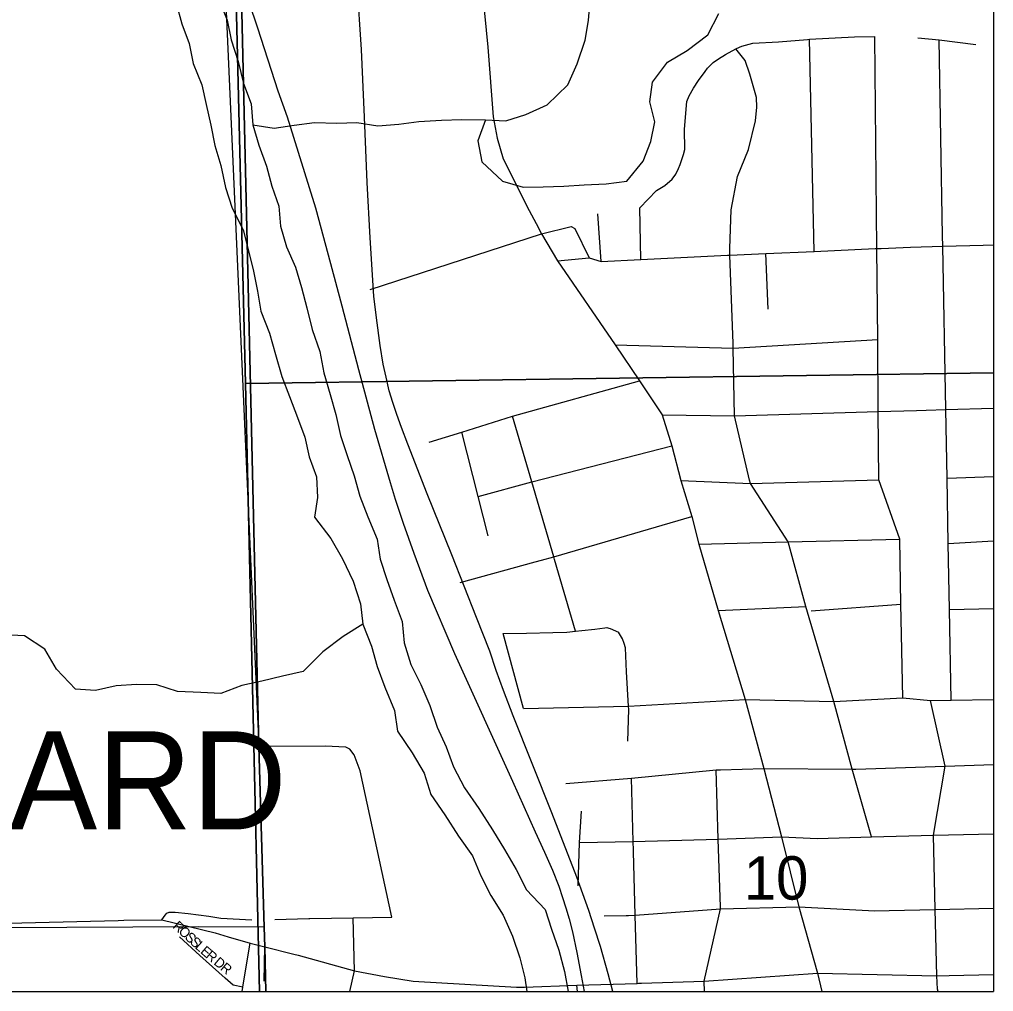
# Model space of a CAD drawing. Extents: x -37878.7 to -37844.7, y -19791.4 to -19769.4.
# Drawn here: x -37870.09 to -37869.15, y -19777.385 to -19776.447 of the extents above; entities that cross this region are included whole.
import ezdxf

# ---------------------------------------------------------------- set-up
doc = ezdxf.new("R2010")
doc.units = 0
for name, color, linetype in [('Default', 7, 'Continuous'), ('GM_X_City_Street', 7, 'Continuous'), ('GM_X_Corporation', 7, 'Continuous'), ('GM_X_Corporation_Text', 7, 'Continuous'), ('GM_X_County_Road', 7, 'Continuous'), ('GM_X_Major_River', 7, 'Continuous'), ('GM_X_Minor_River', 7, 'Continuous'), ('GM_X_Rail_Line', 7, 'Continuous'), ('GM_X_Section', 7, 'Continuous'), ('GM_X_Section_Text', 7, 'Continuous'), ('GM_X_State_Route', 7, 'Continuous'), ('GM_X_Township', 7, 'Continuous'), ('GM_X_US_Route', 7, 'Continuous'), ('SH_Data', 7, 'Continuous')]:
    doc.layers.add(name, color=color, linetype=linetype)

msp = doc.modelspace()

# ---------------------------------------------------------------- linework, layer by layer
at = {"layer": 'Default'}
msp.add_lwpolyline([(-37869.89171, -19777.37255), (-37869.91613, -19777.35058), (-37869.93578, -19777.3327)], dxfattribs=at)
at = {"layer": 'GM_X_City_Street'}
for points in [[(-37869.42351, -19776.49143), (-37869.42092, -19776.48904), (-37869.41566, -19776.4854), (-37869.40897, -19776.48136), (-37869.399, -19776.47578), (-37869.3983, -19776.47539), (-37869.39318, -19776.47327), (-37869.38251, -19776.47039), (-37869.35791, -19776.46895), (-37869.32991, -19776.46666), (-37869.32802, -19776.46656), (-37869.28447, -19776.46427), (-37869.26478, -19776.46373)], [(-37869.32333, -19776.67115), (-37869.32802, -19776.46656)], [(-37869.23922, -19777.04078), (-37869.2398, -19777.01155), (-37869.24069, -19776.94897), (-37869.26114, -19776.89148), (-37869.26153, -19776.82581), (-37869.26194, -19776.75609), (-37869.2628, -19776.66844), (-37869.26478, -19776.46373)], [(-37869.22341, -19776.46526), (-37869.20289, -19776.46697), (-37869.1675, -19776.4717)], [(-37869.19944, -19776.6562), (-37869.19944, -19776.65608), (-37869.20289, -19776.46697)], [(-37869.40479, -19776.66886), (-37869.40478, -19776.66853), (-37869.40349, -19776.63102), (-37869.39723, -19776.59891), (-37869.38663, -19776.57275), (-37869.37987, -19776.54519), (-37869.37873, -19776.53205), (-37869.37902, -19776.52275), (-37869.38537, -19776.50014), (-37869.38993, -19776.48698), (-37869.399, -19776.47578)], [(-37869.49166, -19776.6293), (-37869.47542, -19776.61251), (-37869.46759, -19776.60773), (-37869.46055, -19776.60145), (-37869.45683, -19776.59662), (-37869.45439, -19776.59136), (-37869.45277, -19776.58751), (-37869.44932, -19776.57759), (-37869.44803, -19776.57296), (-37869.44856, -19776.5532), (-37869.44624, -19776.52652), (-37869.44402, -19776.52122), (-37869.43976, -19776.51373), (-37869.4349, -19776.50624), (-37869.42854, -19776.49756), (-37869.42623, -19776.49441), (-37869.42356, -19776.49147), (-37869.42351, -19776.49143)], [(-37869.4907, -19776.67899), (-37869.49166, -19776.6293)], [(-37869.52896, -19776.68086), (-37869.53207, -19776.63498)], [(-37869.5864, -19776.65411), (-37869.5578, -19776.64725), (-37869.55417, -19776.64925), (-37869.54045, -19776.67757)], [(-37869.75193, -19776.70793), (-37869.5864, -19776.65411)], [(-37869.19128, -19777.10438), (-37869.19287, -19777.01691), (-37869.19403, -19776.95308), (-37869.19518, -19776.89004), (-37869.19638, -19776.82384), (-37869.19925, -19776.66614), (-37869.19944, -19776.6562)], [(-37869.2586, -19776.66826), (-37869.23057, -19776.667), (-37869.19925, -19776.66614), (-37869.16047, -19776.66507), (-37869.15036, -19776.66493)], [(-37869.57101, -19776.68032), (-37869.54045, -19776.67757), (-37869.52896, -19776.68086), (-37869.4907, -19776.67899), (-37869.40703, -19776.6749), (-37869.40482, -19776.6748), (-37869.36994, -19776.67324), (-37869.32333, -19776.67115), (-37869.26447, -19776.66852), (-37869.2628, -19776.66844), (-37869.2586, -19776.66826)], [(-37869.26824, -19777.23612), (-37869.2868, -19777.17084), (-37869.30447, -19777.10557), (-37869.33142, -19777.01394), (-37869.34849, -19776.95136), (-37869.38493, -19776.8953), (-37869.38593, -19776.89191), (-37869.40027, -19776.82999), (-37869.40148, -19776.76467), (-37869.40157, -19776.76015), (-37869.40482, -19776.6748), (-37869.40491, -19776.67248), (-37869.40479, -19776.66886)], [(-37869.36774, -19776.72706), (-37869.36994, -19776.67324)], [(-37869.51542, -19776.76123), (-37869.40148, -19776.76467), (-37869.26194, -19776.75609)], [(-37869.69494, -19776.85545), (-37869.66332, -19776.84557), (-37869.61435, -19776.83027), (-37869.49206, -19776.79597)], [(-37869.57392, -19776.96853), (-37869.57392, -19776.96853), (-37869.57468, -19776.96591), (-37869.59589, -19776.89341), (-37869.61435, -19776.83027)], [(-37869.63796, -19776.94554), (-37869.64759, -19776.90758), (-37869.66332, -19776.84557)], [(-37869.64759, -19776.90758), (-37869.59589, -19776.89341), (-37869.46062, -19776.85884)], [(-37869.45194, -19776.89238), (-37869.38493, -19776.8953), (-37869.26114, -19776.89148)], [(-37869.19518, -19776.89004), (-37869.15036, -19776.88847)], [(-37869.58645, -19776.96916), (-37869.57468, -19776.96591), (-37869.44146, -19776.92711)], [(-37869.43457, -19776.95376), (-37869.34849, -19776.95136), (-37869.24069, -19776.94897)], [(-37869.19403, -19776.95308), (-37869.15036, -19776.95056)], [(-37869.66481, -19776.99077), (-37869.59267, -19776.97087), (-37869.58645, -19776.96916)], [(-37869.5537, -19777.03765), (-37869.57392, -19776.96853)], [(-37869.41615, -19777.01784), (-37869.33142, -19777.01394)], [(-37869.32628, -19777.01799), (-37869.2398, -19777.01155)], [(-37869.19287, -19777.01691), (-37869.15036, -19777.01581)], [(-37869.62332, -19777.03983), (-37869.60096, -19777.0396), (-37869.57558, -19777.03891), (-37869.56194, -19777.03853), (-37869.5537, -19777.03765), (-37869.54757, -19777.037), (-37869.53509, -19777.03589), (-37869.52527, -19777.03448), (-37869.5235, -19777.03427), (-37869.52148, -19777.03468), (-37869.52033, -19777.03511), (-37869.51227, -19777.03869)], [(-37869.60396, -19777.11232), (-37869.62332, -19777.03983)], [(-37869.50304, -19777.14378), (-37869.50233, -19777.11334), (-37869.50252, -19777.10993), (-37869.50443, -19777.07689), (-37869.50543, -19777.05371), (-37869.50661, -19777.04966), (-37869.50822, -19777.04521), (-37869.51227, -19777.03869)], [(-37869.238, -19777.10198), (-37869.23922, -19777.04078)], [(-37869.60396, -19777.11232), (-37869.50252, -19777.10993), (-37869.39011, -19777.10377)], [(-37869.39011, -19777.10377), (-37869.30447, -19777.10557), (-37869.238, -19777.10198), (-37869.2112, -19777.10469), (-37869.19128, -19777.10438), (-37869.15036, -19777.10374)], [(-37869.20521, -19777.3702), (-37869.20665, -19777.30615), (-37869.20827, -19777.23464), (-37869.19698, -19777.16785), (-37869.2112, -19777.10469)], [(-37869.73075, -19777.31362), (-37869.76144, -19777.17243), (-37869.7672, -19777.15703), (-37869.77151, -19777.15146), (-37869.77537, -19777.14967), (-37869.79523, -19777.14854), (-37869.85918, -19777.14892)], [(-37869.56305, -19777.18459), (-37869.49966, -19777.17959), (-37869.41795, -19777.17144)], [(-37869.41383, -19777.30364), (-37869.41615, -19777.23851), (-37869.41795, -19777.17144), (-37869.41381, -19777.17133)], [(-37869.41381, -19777.17133), (-37869.37185, -19777.17024)], [(-37869.37185, -19777.17024), (-37869.2868, -19777.17084), (-37869.28336, -19777.17073)], [(-37869.28336, -19777.17073), (-37869.19698, -19777.16785), (-37869.15036, -19777.16627)], [(-37869.49774, -19777.25043), (-37869.49778, -19777.24886), (-37869.498, -19777.24066), (-37869.49966, -19777.17959)], [(-37869.55099, -19777.28329), (-37869.54995, -19777.2415), (-37869.54781, -19777.21148)], [(-37869.54995, -19777.2415), (-37869.498, -19777.24066), (-37869.41615, -19777.23851), (-37869.35507, -19777.23612)], [(-37869.35507, -19777.23612), (-37869.32004, -19777.2376), (-37869.26824, -19777.23612), (-37869.20827, -19777.23464), (-37869.15036, -19777.23311)], [(-37869.49429, -19777.3775), (-37869.49608, -19777.31184), (-37869.49774, -19777.25043)], [(-37869.50246, -19777.31195), (-37869.49608, -19777.31184), (-37869.41376, -19777.30558), (-37869.33831, -19777.30378)], [(-37869.42915, -19777.3854), (-37869.4294, -19777.37537), (-37869.41376, -19777.30558), (-37869.41383, -19777.30364)], [(-37869.33831, -19777.30378), (-37869.26472, -19777.30743), (-37869.25119, -19777.30713)], [(-37869.25119, -19777.30713), (-37869.20665, -19777.30615), (-37869.15036, -19777.3049)], [(-37869.95272, -19777.31614), (-37869.9497, -19777.31163), (-37869.94803, -19777.30968), (-37869.94581, -19777.30885), (-37869.93998, -19777.30885), (-37869.92748, -19777.31024), (-37869.90748, -19777.31274), (-37869.89582, -19777.31468), (-37869.86609, -19777.31635)], [(-37869.84374, -19777.31604), (-37869.81096, -19777.31493), (-37869.80985, -19777.31492)], [(-37869.80985, -19777.31492), (-37869.76805, -19777.31438), (-37869.73075, -19777.31362)], [(-37869.77142, -19777.3854), (-37869.7669, -19777.36544), (-37869.76805, -19777.31438)], [(-37869.52594, -19777.31235), (-37869.50472, -19777.31199), (-37869.50246, -19777.31195)], [(-37869.88864, -19777.33263), (-37869.86745, -19777.33876)], [(-37869.87464, -19777.38083), (-37869.86745, -19777.33876), (-37869.85352, -19777.34229), (-37869.82538, -19777.34942)], [(-37869.85408, -19777.37526), (-37869.85352, -19777.34229)], [(-37869.82538, -19777.34942), (-37869.82135, -19777.35044), (-37869.7669, -19777.36544), (-37869.73802, -19777.371), (-37869.71024, -19777.37545), (-37869.61059, -19777.38133), (-37869.60291, -19777.38108)], [(-37869.49013, -19777.37737), (-37869.4294, -19777.37537), (-37869.32034, -19777.36756)], [(-37869.32034, -19777.36756), (-37869.20521, -19777.3702), (-37869.19303, -19777.36995)], [(-37869.20365, -19777.3854), (-37869.20433, -19777.38304), (-37869.20521, -19777.3702)], [(-37869.19303, -19777.36995), (-37869.15036, -19777.36909)], [(-37869.87467, -19777.38106), (-37869.88412, -19777.37939), (-37869.89171, -19777.37255)], [(-37869.60291, -19777.38108), (-37869.55234, -19777.37941), (-37869.49429, -19777.3775), (-37869.49282, -19777.37746), (-37869.49013, -19777.37737)], [(-37869.55169, -19777.3854), (-37869.55234, -19777.37941)]]:
    msp.add_lwpolyline(points, dxfattribs=at)
at = {"layer": 'GM_X_Corporation'}
msp.add_lwpolyline([(-37871.03403, -19775.9918), (-37870.99201, -19775.97355), (-37870.94517, -19775.95099), (-37870.84307, -19775.92314), (-37870.77311, -19775.89957), (-37870.66134, -19775.87906), (-37870.60841, -19775.87192), (-37870.57174, -19775.88158), (-37870.49365, -19775.92282), (-37870.43119, -19775.96145), (-37870.34642, -19775.99718), (-37870.23698, -19776.04785), (-37870.09353, -19776.15235), (-37869.98605, -19776.25974), (-37869.96006, -19776.31113), (-37869.9401, -19776.36422), (-37869.92905, -19776.41032), (-37869.89186, -19776.41045), (-37869.85918, -19777.14892), (-37869.85397, -19777.32346), (-37869.91698, -19777.32303), (-37870.36299, -19777.3253), (-37870.36151, -19777.3854)], dxfattribs=at)
at = {"layer": 'GM_X_County_Road'}
for points in [[(-37870.35276, -19777.32526), (-37870.34053, -19777.3252), (-37869.99484, -19777.31682)], [(-37869.99484, -19777.31682), (-37869.98938, -19777.31669), (-37869.95272, -19777.31614)], [(-37869.95272, -19777.31614), (-37869.90148, -19777.32892), (-37869.88864, -19777.33263)], [(-37869.87529, -19777.3854), (-37869.87467, -19777.38106), (-37869.87464, -19777.38083)]]:
    msp.add_lwpolyline(points, dxfattribs=at)
at = {"layer": 'GM_X_Major_River'}
for points in [[(-37869.90547, -19776.40835), (-37869.88982, -19776.44792), (-37869.88577, -19776.46693), (-37869.87909, -19776.48785), (-37869.87392, -19776.50914), (-37869.86647, -19776.52893), (-37869.86509, -19776.54906), (-37869.85915, -19776.56884), (-37869.85171, -19776.589), (-37869.84653, -19776.6084), (-37869.83984, -19776.62742), (-37869.83844, -19776.6468), (-37869.83251, -19776.66695), (-37869.82393, -19776.68637), (-37869.81799, -19776.70614), (-37869.81282, -19776.72554), (-37869.80765, -19776.74645), (-37869.80021, -19776.76776), (-37869.79656, -19776.78828), (-37869.79025, -19776.8092), (-37869.78507, -19776.8286), (-37869.78028, -19776.84875), (-37869.77396, -19776.86815), (-37869.76728, -19776.88793), (-37869.76172, -19776.90732), (-37869.7539, -19776.92749), (-37869.74494, -19776.9488), (-37869.74204, -19776.96819), (-37869.73573, -19776.98797), (-37869.72866, -19777.00775), (-37869.72084, -19777.0283), (-37869.71908, -19777.04882), (-37869.7124, -19777.06974), (-37869.70305, -19777.08915), (-37869.69409, -19777.10932), (-37869.68703, -19777.13024), (-37869.67845, -19777.14927), (-37869.67137, -19777.16868), (-37869.6609, -19777.18886), (-37869.64702, -19777.20867), (-37869.6339, -19777.22924), (-37869.62229, -19777.24829), (-37869.61105, -19777.26771), (-37869.60095, -19777.28713), (-37869.5829, -19777.3062), (-37869.57696, -19777.32522), (-37869.5699, -19777.34538), (-37869.56435, -19777.36592), (-37869.56069, -19777.38531), (-37869.56069, -19777.3854)], [(-37869.93893, -19776.43174), (-37869.93338, -19776.45152), (-37869.92631, -19776.47054), (-37869.92264, -19776.48993), (-37869.91406, -19776.51047), (-37869.91002, -19776.52949), (-37869.9056, -19776.54925), (-37869.90156, -19776.56903), (-37869.896, -19776.58842), (-37869.89121, -19776.60971), (-37869.8849, -19776.62949), (-37869.87443, -19776.65043), (-37869.86926, -19776.67058), (-37869.86446, -19776.69036), (-37869.86042, -19776.70974), (-37869.85713, -19776.72875), (-37869.84894, -19776.75006), (-37869.84301, -19776.7706), (-37869.83709, -19776.79189), (-37869.82964, -19776.8113), (-37869.82182, -19776.83147), (-37869.81474, -19776.85049), (-37869.8107, -19776.8695), (-37869.80363, -19776.8889), (-37869.80262, -19776.90866), (-37869.80539, -19776.92764), (-37869.78962, -19776.94822), (-37869.77838, -19776.96802), (-37869.7683, -19776.98934), (-37869.76124, -19777.0114), (-37869.75871, -19777.03078), (-37869.75052, -19777.05209), (-37869.74497, -19777.07187), (-37869.73752, -19777.09165), (-37869.7282, -19777.1141), (-37869.7253, -19777.13425), (-37869.71142, -19777.1552), (-37869.69981, -19777.17463), (-37869.69312, -19777.19517), (-37869.67962, -19777.21498), (-37869.6665, -19777.23555), (-37869.65299, -19777.2546), (-37869.64516, -19777.27363), (-37869.63544, -19777.29267), (-37869.62344, -19777.31171), (-37869.61449, -19777.33189), (-37869.60743, -19777.35281), (-37869.60263, -19777.3722), (-37869.60076, -19777.3854)]]:
    msp.add_lwpolyline(points, dxfattribs=at)
at = {"layer": 'GM_X_Minor_River'}
for points in [[(-37869.86509, -19776.54906), (-37869.84428, -19776.5522), (-37869.82496, -19776.54925), (-37869.80563, -19776.54668), (-37869.78406, -19776.54754), (-37869.76475, -19776.54686), (-37869.74432, -19776.55), (-37869.72425, -19776.54857), (-37869.70492, -19776.546), (-37869.68295, -19776.54458), (-37869.66326, -19776.54391), (-37869.64055, -19776.54439), (-37869.62087, -19776.54524), (-37869.60152, -19776.53925), (-37869.58102, -19776.52985), (-37869.56121, -19776.51057), (-37869.552, -19776.4901), (-37869.54428, -19776.46735), (-37869.54113, -19776.44837), (-37869.53949, -19776.42787)], [(-37869.64055, -19776.54439), (-37869.64787, -19776.56449), (-37869.64421, -19776.58464), (-37869.62426, -19776.60334), (-37869.60423, -19776.60913), (-37869.58492, -19776.60883), (-37869.56485, -19776.60817), (-37869.54516, -19776.60712), (-37869.52395, -19776.60607), (-37869.50425, -19776.6035), (-37869.48823, -19776.5842), (-37869.48091, -19776.56525), (-37869.47701, -19776.54627), (-37869.48181, -19776.52688), (-37869.47942, -19776.5079), (-37869.46491, -19776.4886), (-37869.44591, -19776.47729), (-37869.42613, -19776.46218), (-37869.4154, -19776.44172)], [(-37869.75871, -19777.03078), (-37869.77772, -19777.04285), (-37869.7975, -19777.05757), (-37869.81655, -19777.07648), (-37869.83627, -19777.08094), (-37869.85636, -19777.08579), (-37869.8757, -19777.09025), (-37869.89581, -19777.09776), (-37869.91512, -19777.09691), (-37869.93783, -19777.09604), (-37869.95747, -19777.0895), (-37869.97716, -19777.08902), (-37869.99685, -19777.09045), (-37870.01695, -19777.09491), (-37870.03625, -19777.09369), (-37870.05429, -19777.07423), (-37870.06553, -19777.05519), (-37870.08514, -19777.04218), (-37870.10482, -19777.04133)]]:
    msp.add_lwpolyline(points, dxfattribs=at)
at = {"layer": 'GM_X_Rail_Line'}
for points in [[(-37869.88583, -19776.37974), (-37869.8606, -19776.45544), (-37869.84075, -19776.51636), (-37869.83188, -19776.54127), (-37869.80453, -19776.62911), (-37869.79018, -19776.68274), (-37869.7792, -19776.72371), (-37869.76294, -19776.78526), (-37869.74763, -19776.84259), (-37869.73264, -19776.89421), (-37869.72767, -19776.91037), (-37869.72007, -19776.93349), (-37869.70973, -19776.96242), (-37869.69642, -19776.998), (-37869.67045, -19777.05923), (-37869.6146, -19777.18233), (-37869.59254, -19777.23132), (-37869.58356, -19777.25085), (-37869.57575, -19777.26827), (-37869.56973, -19777.28379), (-37869.56614, -19777.29456), (-37869.56287, -19777.3047), (-37869.55991, -19777.31525), (-37869.55664, -19777.32771), (-37869.55231, -19777.34788), (-37869.54809, -19777.36984), (-37869.54525, -19777.3854)], [(-37869.51766, -19777.3854), (-37869.52213, -19777.36833), (-37869.5296, -19777.34205), (-37869.53527, -19777.32414), (-37869.54094, -19777.30713), (-37869.55228, -19777.27492), (-37869.5765, -19777.21308), (-37869.61374, -19777.11928), (-37869.62301, -19777.09493), (-37869.63023, -19777.07561), (-37869.63641, -19777.05705), (-37869.64917, -19777.02446), (-37869.67313, -19776.96416), (-37869.69671, -19776.90515), (-37869.71539, -19776.85735), (-37869.7217, -19776.84112), (-37869.72609, -19776.82875), (-37869.72995, -19776.8169), (-37869.7333, -19776.80569), (-37869.73639, -19776.79267), (-37869.73936, -19776.78018), (-37869.74219, -19776.76201), (-37869.7458, -19776.73534), (-37869.74812, -19776.71447), (-37869.75185, -19776.65804), (-37869.75469, -19776.60457), (-37869.75739, -19776.54156), (-37869.76001, -19776.47638), (-37869.76439, -19776.41313)]]:
    msp.add_lwpolyline(points, dxfattribs=at)
at = {"layer": 'GM_X_Section'}
for points in [[(-37869.15036, -19776.78842), (-37869.87222, -19776.79874), (-37869.88389, -19776.31106), (-37869.89663, -19775.75004), (-37869.15036, -19775.742)], [(-37870.98026, -19777.3854), (-37871.00738, -19776.32795), (-37869.88389, -19776.31106), (-37869.87222, -19776.79874), (-37869.85861, -19777.3854)], [(-37869.85861, -19777.3854), (-37869.87222, -19776.79874), (-37869.15036, -19776.78842)]]:
    msp.add_lwpolyline(points, dxfattribs=at)
at = {"layer": 'GM_X_State_Route'}
for points in [[(-37869.4702, -19776.8289), (-37869.40027, -19776.82999), (-37869.26153, -19776.82581), (-37869.22451, -19776.82469), (-37869.21525, -19776.82441)], [(-37869.21525, -19776.82441), (-37869.19638, -19776.82384), (-37869.15036, -19776.82245)]]:
    msp.add_lwpolyline(points, dxfattribs=at)
at = {"layer": 'GM_X_Township'}
for points in [[(-37869.85249, -19777.3854), (-37869.85352, -19777.34229), (-37869.85397, -19777.32346), (-37869.85918, -19777.14892), (-37869.88906, -19775.85642), (-37869.89931, -19775.42763), (-37869.90245, -19775.29641), (-37869.90694, -19775.1088), (-37869.90874, -19775.03358), (-37869.90889, -19775.02744), (-37869.91269, -19774.86837)], [(-37869.91269, -19774.86837), (-37869.90889, -19775.02744), (-37869.90874, -19775.03358), (-37869.90694, -19775.1088), (-37869.90245, -19775.29641), (-37869.89931, -19775.42763), (-37869.88906, -19775.85642), (-37869.85918, -19777.14892), (-37869.85397, -19777.32346), (-37869.85352, -19777.34229), (-37869.85249, -19777.3854)]]:
    msp.add_lwpolyline(points, dxfattribs=at)
at = {"layer": 'GM_X_US_Route'}
for points in [[(-37870.03845, -19775.67615), (-37869.97335, -19775.75551), (-37869.88906, -19775.85642), (-37869.83841, -19775.92369), (-37869.79226, -19775.98001), (-37869.76012, -19776.02409), (-37869.74495, -19776.05231), (-37869.74214, -19776.06778), (-37869.72878, -19776.10504), (-37869.70805, -19776.16057), (-37869.68242, -19776.22845), (-37869.66509, -19776.27787), (-37869.65162, -19776.33628), (-37869.63814, -19776.47428), (-37869.63312, -19776.54129), (-37869.62913, -19776.5618), (-37869.62344, -19776.58175), (-37869.59836, -19776.63189), (-37869.59164, -19776.64438)], [(-37869.59164, -19776.64438), (-37869.5864, -19776.65411), (-37869.57101, -19776.68032), (-37869.51542, -19776.76123), (-37869.49206, -19776.79597), (-37869.4702, -19776.8289)], [(-37869.4702, -19776.8289), (-37869.46062, -19776.85884), (-37869.45194, -19776.89238), (-37869.44146, -19776.92711), (-37869.43457, -19776.95376), (-37869.41615, -19777.01784), (-37869.39011, -19777.10377), (-37869.37185, -19777.17024), (-37869.35507, -19777.23612), (-37869.33831, -19777.30378), (-37869.32034, -19777.36756), (-37869.31585, -19777.3854)]]:
    msp.add_lwpolyline(points, dxfattribs=at)
at = {"layer": 'SH_Data'}
for p in [(-37869.15036, -19770.3854), (-37876.15036, -19777.3854)]:
    msp.add_line(p, (-37869.15036, -19777.3854), dxfattribs=at)

# ---------------------------------------------------------------- texts
at = {"layer": 'Default'}
for s, rotation, p in [('R', 317.6626, (-37869.94299, -19777.32336)), ('O', 317.64397, (-37869.93744, -19777.32841)), ('S', 317.67147, (-37869.93128, -19777.33403)), ('S', 317.67147, (-37869.92635, -19777.33852)), ('L', 317.7956, (-37869.92141, -19777.34302)), ('E', 319.17646, (-37869.91629, -19777.34767)), ('R', 320.16228, (-37869.91111, -19777.35214)), ('D', 320.20576, (-37869.90342, -19777.35855)), ('R', 320.20065, (-37869.89702, -19777.36388))]:
    msp.add_text(s, height=0.00947, rotation=rotation, dxfattribs=at).set_placement(p)
at = {"layer": 'GM_X_Corporation_Text'}
msp.add_text('GIRARD', height=0.094696, rotation=0.00001, dxfattribs=at).set_placement((-37870.32478, -19777.22896))
at = {"layer": 'GM_X_Section_Text'}
msp.add_text('10', height=0.041856, rotation=0.00001, dxfattribs=at).set_placement((-37869.39127, -19777.2967))

doc.saveas('drawing.dxf')
